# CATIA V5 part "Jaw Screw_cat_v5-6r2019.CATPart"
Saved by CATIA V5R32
Part number: Jaw Screw
Bounding box of the stored display mesh (mm): x -9 to 9, y 0 to 138, z -8.948 to 9
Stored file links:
  D:\PROJECTS\Project 2022\CATIA V5 6R 2022\Resources\Tutorial Files\c16_catia_v5_6r2022_tut\Bench vice\Jaw Screw_cat_v5-6r2019.CATPart
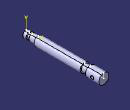
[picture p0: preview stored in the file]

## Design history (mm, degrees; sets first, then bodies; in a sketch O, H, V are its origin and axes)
Body1 (main body)
  Sketch1 on yz-plane, origin (0, 0, 0), H (0, 1, 0), V (0, 0, 1)
    line L1 (0, 0) -> (0, 6)
    line L2 (0, 6) -> (6, 6)
    line L3 (6, 6) -> (6, 4)
    line L4 (6, 4) -> (11, 4)
    line L5 (11, 4) -> (11, 6)
    point P5 (11, 6)
    line L6 (11, 6) -> (22, 6)
    line L7 (22, 6) -> (22, 8)
    line L8 (22, 8) -> (104, 8)
    line L9 (104, 8) -> (104, 6)
    point P9 (104, 6)
    line L10 (104, 6) -> (114, 6)
    line L11 (114, 6) -> (114, 9)
    line L12 (114, 9) -> (138, 9)
    line L13 (138, 9) -> (138, 0)
    point P13 (138, 0)
    line L14 (138, 0) -> (0, 0)
    distance L2 L14 = 6
    distance L8 L14 = 8
    distance L12 L14 = 9
    length L2 = 6
    length L4 = 5
    length L8 = 82
    length L10 = 10
    length L12 = 24
    length L14 = 138
    distance L4 L14 = 4
    vertical: L1 V, L3 V, L5 V, L7 V, L9 V, L11 V, L13 V
    horizontal: L2 H, L4 H, L6 H, L8 H, L10 H, L12 H, L14 H
    coincidence: P5 L2, P9 L6, P13 H
  Shaft1: profile Sketch1, axis edge of Sketch1, angle 360
  Sketch2 on yz-plane, origin (0, 0, 0), H (0, 1, 0), V (0, 0, 1)
    circle A1 centre (126, 0) radius 3
    point P1 (126, 0)
    radius A1 = 3
    distance P1 V = 126
    coincidence: P1 H
  Pocket1: profile Sketch2, direction (-1, 0, 0), length 20, mirrored extent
